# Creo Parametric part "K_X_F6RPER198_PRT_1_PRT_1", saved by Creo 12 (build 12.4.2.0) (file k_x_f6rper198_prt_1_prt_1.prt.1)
Units: Custom; MM, KILOGRAM, SECS

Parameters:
  PTC_WM_ITERATION = "0"
  PTC_WM_VERSION = "-.0"
  PTC_WM_LIFECYCLE_STATE = "In Work"
  PTC_WM_LIFECYCLE = "MO_CADDocument"
  PTC_WM_CREATED_BY = "Maximilian Roepper (Z0017RMS: MO)"
  PTC_WM_CREATED_ON = "18-Sep-26 11:36:42 AM"
  PTC_WM_MODIFIED_BY = "Maximilian Roepper (Z0017RMS: MO)"
  PTC_WM_MODIFIED_ON = "18-Sep-26 11:36:46 AM"
  PDMLINKNUMBER = "PDM000071455337"
  PTC_WM_NAME = "k_x_f6rper198_prt_1_prt_1.prt"
  PTC_WM_NUMBER = "PDM000071455337"

Other parameters: WEIGHT, WEIGHT_FACTOR, WEIGHT_ADD, _MASS_TEMP, _DIFF_TEMP, MC_ERRORS, SUPPLIER

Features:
  1. coordinate system
  2. datum plane "PRT_YZ"
  3. datum plane "PRT_XY"
  4. datum plane "PRT_XZ"
  5. coordinate system
  6. datum axis
  7. datum axis
  8. datum axis
  9. coordinate system
  10. imported feature
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
Other named items: PRT, SIEMENS_MO, DRW_VIEW_ORG, PRT_X, PRT_Y, PRT_Z, CS0, ROUGH_GROB

Layers: 00_STD_CSYS-KSYS, 01_STD_PLANES-EBENEN, 02_STD_AXES-ACHSEN, 03_STD_CSYS-KSYS, 24_IMPORT_FEAT-IMPORT_KE

Surfaces: 14 plane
